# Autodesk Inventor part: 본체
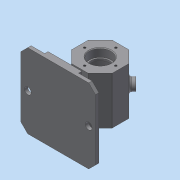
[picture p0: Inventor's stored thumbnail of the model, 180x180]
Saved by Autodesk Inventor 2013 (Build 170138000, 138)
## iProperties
Created: 2018-06
Part Number: 본체
Material: 일반
Document SubType Name: Modeling
Designer: Administrator
Density: 1 g/cm^3
Author: Administrator
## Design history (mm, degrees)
sketch "스케치2" dims "d0" = 60
  geometry: L1 (12.426, 30)-(30, 12.426); L2 (30, 12.426)-(30, -12.426); L3 (30, -12.426)-(12.426, -30); L4 (12.426, -30)-(-12.426, -30); L5 (-12.426, -30)-(-30, -12.426); L6 (-30, -12.426)-(-30, 12.426); L7 (-30, 12.426)-(-12.426, 30); L8 (-12.426, 30)-(12.426, 30); L9 (-55, -62)-(55, -62); L10 (55, -62)-(55, -57); L11 (55, -57)-(25, -57); L12 (25, -57)-(25, -52); L13 (25, -52)-(-25, -52); L14 (-25, -52)-(-25, -57); L15 (-25, -57)-(-55, -57); L16 (-55, -57)-(-55, -62); L17 (0, 0)-(0, -62); L18 (-5, -30)-(-5, -52); L19 (5, -30)-(5, -52); 3 further points
  constraints: 38 end point, 7 parallel, 4 point on line, 3 perpendicular, 2 coincident, 2 midpoint, 2 vertical alignment, 1 collinear, 1 vertical, 21 other
  dimensions: "d4" = 62 distance of L17.start L17.end; "d5" = 10 distance between parallel lines of L9 L13; "d6" = 5 distance between parallel lines of L9 L15; "d7" = 110 distance of L9.start L9.end; "d8" = 30 distance of L14.end L15.end; "d9" = 10 distance between parallel lines of L18 L19
extrude "돌출1" new body sketch "스케치2" distance "d2" = 35; taper "d3" = 0 deg
extrude "돌출2" join sketch "스케치2" distance "d10" = 55; taper "d11" = 0 deg
extrude "돌출3" join sketch "스케치2" distance "d12" = 24; taper "d13" = 0 deg
chamfer "모따기1" distance "d14" = 10; stored, may be unused: second distance "d15" = 2, angle "d16" = 45 deg
fillet "모깎기1" dims "d17" = 5
hole "구멍1" sketch "스케치2" diameter "d18" = 28; stored, may be unused: countersink angle "d22" = 90 deg, drill point angle "d24" = 118 deg; dims "d19" = 6, "d20" = 50, "d21" = 20, "d23" = 8
hole "구멍2" diameter "d27" = 28; stored, may be unused: countersink angle "d31" = 90 deg, drill point angle "d33" = 118 deg; dims "d25" = 10, "d26" = 10, "d28" = 6, "d29" = 32, "d30" = 12, "d32" = 8
sketch "스케치3"
  geometry: C1 r 8 at (-12.426, 35); 1 further point
  constraints: 1 centre point, 1 coincident
  dimensions: "d35" = 16 diameter of C1
extrude "돌출4" join sketch "스케치3" distance "d36" = 7; taper "d37" = 0 deg
sketch "스케치4"
  geometry: L1 (24.853, 0)-(0, 0) reference; L2 (-17.574, 0)-(-17.574, 70) reference; 2 further points
  constraints: 1 coincident, 1 other
  dimensions: "d78" = 30 distance from line of L2 point (12.426, 35); "d79" = 35 distance from line of L1 point (12.426, 35)
feature "엠보싱1" sketch "스케치4" dims "d0" = 60, "d4" = 62, "d5" = 10, "d6" = 5, "d7" = 110, "d8" = 30, "d9" = 10, "d38" = 0.5, "d39" = 0
hole "구멍3" diameter "d42" = 8; stored, may be unused: countersink angle "d46" = 90 deg, drill point angle "d48" = 118 deg; dims "d40" = 10, "d41" = 10, "d43" = 6, "d44" = 32, "d45" = 12, "d47" = 8
sketch "스케치5"
  geometry: L1 (-10, 100)-(-10, 10) reference; L2 (20, 0)-(0, 0) reference; 2 further points
  dimensions: "d49" = 10 distance from line of L1 point (0, 55); "d50" = 55 distance from line of L2 point (0, 55)
hole "구멍4" sketch "스케치5" at (0, 55) diameter "d51" = 10; stored, may be unused: countersink angle "d55" = 90 deg, drill point angle "d57" = 118 deg; dims "d52" = 6, "d53" = 32, "d54" = 12, "d56" = 8
sketch "스케치6" dims "d58" = 46
  geometry: C1 r 16 at (0, 0) reference; 2 further points
  constraints: 2 vertical alignment, 1 coincident, 2 other
hole "구멍5" sketch "스케치6" at (0, 23) diameter "d60" = 3.242; stored, may be unused: countersink angle "d64" = 90 deg, drill point angle "d66" = 118 deg; dims "d61" = 8, "d62" = 32, "d63" = 12, "d65" = 10
fillet "모깎기2" dims "d70" = 2
fillet "모깎기3" dims "d71" = 0.3
fillet "모깎기4" dims "d72" = 3
fillet "모깎기5" dims "d73" = 1
chamfer "모따기2" distance "d74" = 1; stored, may be unused: second distance "d75" = 2, angle "d76" = 45 deg
node "솔리드1"
mirror "대칭1"
mirror "대칭2"
pattern_circular "원형 패턴1" dims angle "d68" = 360 deg
mirror "대칭3"
